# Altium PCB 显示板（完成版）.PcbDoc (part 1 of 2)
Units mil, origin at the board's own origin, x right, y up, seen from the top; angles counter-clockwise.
Board outline 5885.4 x 1803.57 mil, 2 copper layers (TOP, BOOTOM); 110 components, 88 nets, 770 pads, 302 vias.
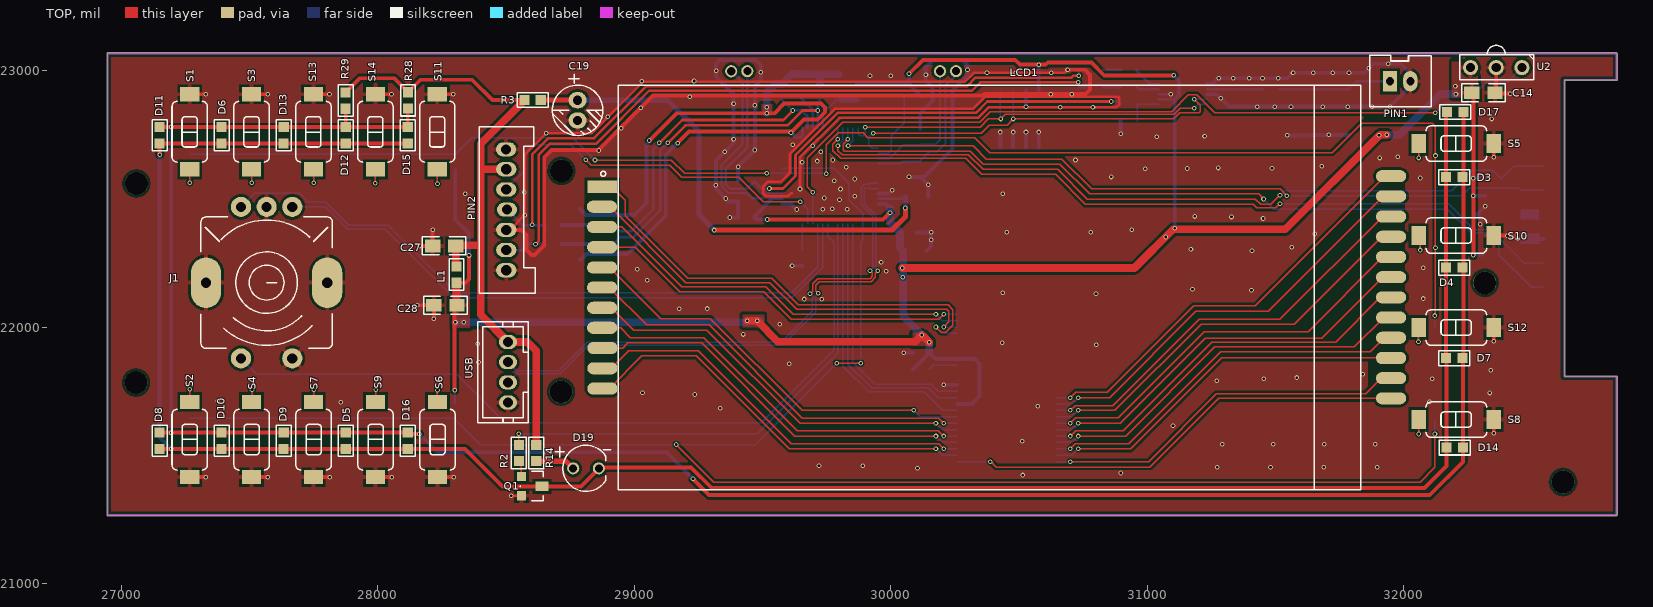
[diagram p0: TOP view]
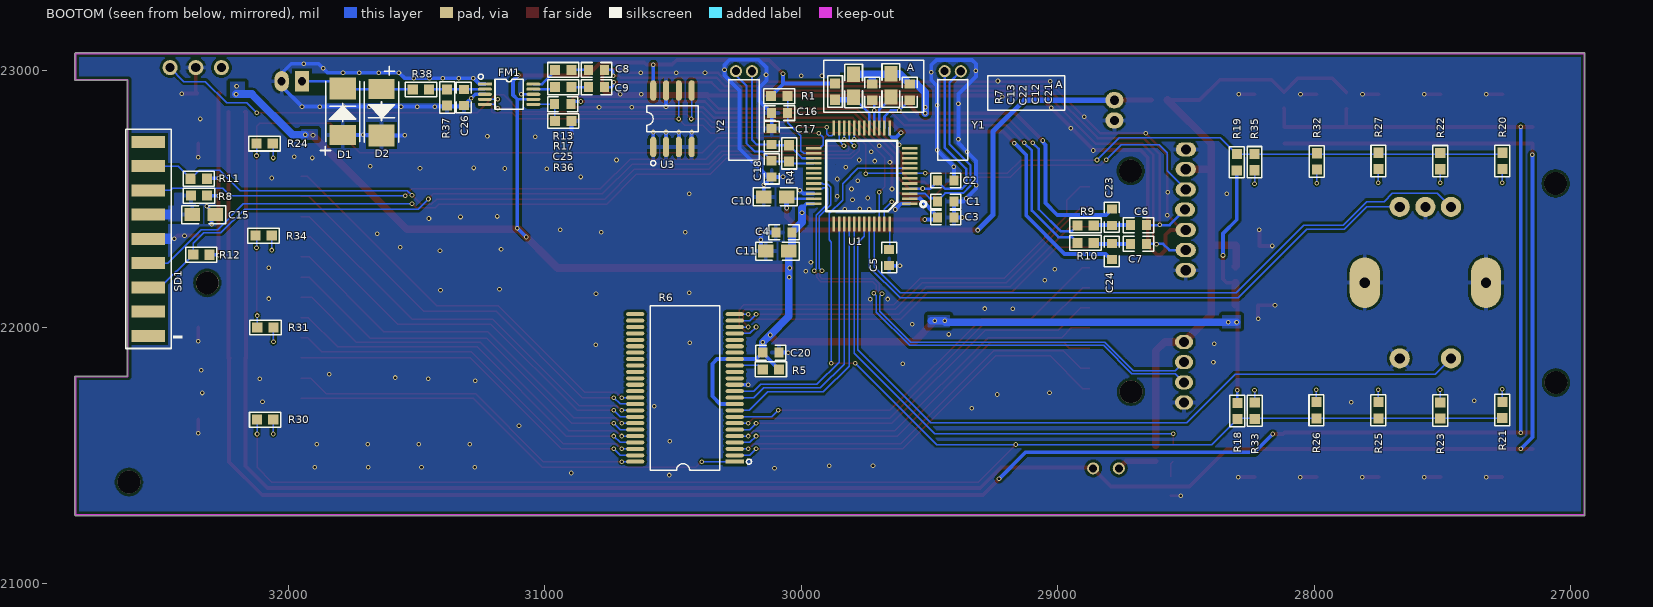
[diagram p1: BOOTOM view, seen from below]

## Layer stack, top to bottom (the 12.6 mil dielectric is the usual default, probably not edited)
TOP: signal copper 1.4
Dielectric: core 12.6, FR-4, Dk 4.8
BOOTOM: signal copper 1.4

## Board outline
26948.18,21265.88 28917.3,21265.88 ccw(c28917.3,21268.39) 28917.34,21265.88 32828.55,21265.88 ccw(c32828.55,21268.39) 32831.07,21268.39 32831.07,21807.05 ccw(c32828.55,21807.05) 32828.55,21809.56 32626.93,21809.56 32626.93,22962.36 32828.55,22962.36 ccw(c32828.55,22964.87) 32831.07,22964.87 32831.07,23066.93 ccw(c32828.55,23066.93) 32828.55,23069.45 26948.18,23069.45 ccw(c26948.18,23066.93) 26945.67,23066.93 26945.67,21295.39 ccw(c26948.18,21295.39) 26945.67,21295.36 26945.67,21268.39 ccw(c26948.18,21268.39)

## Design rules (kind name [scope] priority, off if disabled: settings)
Clearance VIA-POLY [(IsVia) vs INPOLY] p1: gap=5
Clearance POLY [(INPolygon)] p2: gap=10
Clearance ALL [All] p3: gap=5
DiffPairsRouting [(InDifferentialPairClass('90OM'))] p1: maxlimit=7 minlimit=7 mostfreqgap=7 maxuncoupledlength=500
HoleToHoleClearance [All] p1: gap=2 allowstackedmicrovias=TRUE
MatchedLengths DiffPair_90MatchedLengths [InDifferentialPair ('D_D')] p1: tolerance=1000 checknetsindiffpair=TRUE checkdiffpairvsdiffpair=TRUE checkothers=TRUE
NetAntennae [All] p1: netantennaetolerance=2
PlaneClearance [All] p1: clearance=8
PlaneConnect [All] p1: planeconnectstyle=Direct reliefexpansion=20 reliefentries=4 reliefconductorwidth=10 reliefairgap=10
PolygonConnect VIA-POLY0 [ISVIA] p1: connectstyle=Direct reliefconductorwidth=10 reliefentries=4 polygonreliefangle="90 Angle"
PolygonConnect [All] p2: connectstyle=Relief reliefconductorwidth=15 reliefentries=4 polygonreliefangle="90 Angle"
RoutingVias [All] p1: holewidth=10 width=18 viastyle="Through Hole" minholewidth=10 minwidth=18 maxholewidth=10 maxwidth=18
SilkToSilkClearance [All] p1: silktosilkclearance=2
SilkscreenOverComponentPads [All] p1: minsilkscreentomaskgap=2
SolderMaskExpansion [All] p1: expansion=2.5
Width Width90 [(InDifferentialPairClass('90OM'))] p1: maxlimit=5 minlimit=5 preferedwidth=5
Width PWR [InNetClass('PWR')] p2: maxlimit=60 minlimit=15 preferedwidth=15
Width ALLWidth [All] p3: maxlimit=5 minlimit=5 preferedwidth=5
21 further rules are at their usual default settings.

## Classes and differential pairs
differential pair class 90OM: D_D
net class SEG: COM0 COM1 COM2 COM3 SEG0 SEG1 SEG2 SEG3 SEG4 SEG5 SEG6 SEG7 SEG8 SEG9 SEG10 SEG11 SEG12 SEG13 SEG14 SEG15 SEG16 SEG17 SEG18
net class PWR: +5_0V AGND GND KEY_GND NetC10_1 SDVDD VDD33
differential pair D_D: +D+ -D-

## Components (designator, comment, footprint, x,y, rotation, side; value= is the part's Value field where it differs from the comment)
C1 "20P" C0603 29436.5,22490 r0 bottom locked
C2 "20P" C0603 29436.5,22572 r0 bottom locked
C3 "104" C0603 29436.5,22428 r180 bottom locked
C4 "104" C0603 30067.5,22370 r180 bottom locked
C5 "105" C0603 29657,22271.5 r90 bottom locked
C6 "105" C0603 28685.5,22398 r0 bottom locked
C7 "105" C0603 28685.5,22325 r0 bottom locked
C8 "105" C0603 30797.5,23003.05 r0 bottom locked
C9 "105" C0603 30797.5,22936.05 r0 bottom locked
C10 "106" C0805 30101,22508 r0 bottom locked
C11 "106" C0805 30093,22297 r180 bottom locked
C12 "106" C0805 29650,22942.5 r270 bottom locked
C13 "106" C0805 29796,22941 r90 bottom locked
C14 "106" C0805 32310,22914 r0 top locked
C15 "106" C0805 32329,22439 r0 bottom locked
C16 "NC" C0603 30084.5,22835 r180 bottom locked
C17 "10P" C0603 30115,22743.5 r270 bottom locked
C18 "10P" C0603 30115,22617.5 r90 bottom locked
C19 "220uF" EC_5 28779,22885 r270 top locked
C20 "0.1uF" C0603 30118.5,21901 r180 bottom locked
C21 "30" C0603 29577,22916.5 r270 bottom locked
C22 "30" C0603 29723,22916.5 r270 bottom locked
C23 "102" C0603 28789,22429 r270 bottom locked
C24 "102" C0603 28789,22295.5 r270 bottom locked
C25 "100pF" C0603 30929.62,22870 r180 bottom locked
C26 "18pF" C0603 31315,22895.5 r90 bottom locked
C27 "106" C0805 28259,22317 r180 top locked
C28 "106" C0805 28264,22086 r180 top locked
D1 "IN4148" DIODE 31787,22840.45 r270 bottom locked
D2 "IN4148" DIODE 31636,22838.45 r90 bottom locked
D3 "LED" R0603 32196.38,22585.05 r90 top locked
D4 "LED" R0603 32196.38,22232.37 r90 top locked
D5 "LED" R0603 27875.24,21557.62 r180 top locked
D6 "LED" R0603 27391.71,22748.38 r180 top locked
D7 "LED" R0603 32196.38,21879.68 r90 top locked
D8 "LED" R0603 27149.95,21557.62 r180 top locked
D9 "LED" R0603 27633.47,21557.62 r180 top locked
D10 "LED" R0603 27391.71,21557.62 r180 top locked
D11 "LED" R0603 27149.95,22748.38 r180 top locked
D12 "LED" R0603 27875.24,22748.38 r180 top locked
D13 "LED" R0603 27633.47,22748.38 r180 top locked
D14 "LED" R0603 32198.38,21531.05 r90 top locked
D15 "LED" R0603 28117,22748.38 r180 top locked
D16 "LED" R0603 28117,21557.62 r180 top locked
D17 "LED" R0603 32200.38,22839.05 r90 top locked
D19 "LED" BTLED 28804.97,21427.79 r0 top locked
FM1 "RDA5807M" RDA5807M 31138.51,22908.32 r180 bottom locked
J1 "编码器" ENCODE1 27567,22174 r0 top locked
L1 "" R0603 28306.95,22205.38 r180 top locked
LCD1 "23PINLCD" LCD22PIN 29864,22592.3 r0 top locked
PIN1 "2PIN" P2.0*2 32025,22959 r180 top locked
PIN2 "7PIN" P2.0*7 28500.49,22605.48 r0 top locked
Q1 "S8050" SOT-23 28600,21380.5 r270 top locked
R1 "10K" R0603 30085.62,22901.05 r270 bottom locked
R2 "10K" R0603 28550.05,21509.62 r180 top locked
R3 "2R2" R0603 28604,22886 r270 top locked
R4 "10M" R0603 30047,22678 r180 bottom locked
R5 "200R" R0603 30118.38,21835.95 r90 bottom locked
R6 "HT621B-A" YF1621 30471.69,21783.27 r0 bottom locked
R7 "4R7" R0603 29867.95,22918.62 r180 bottom locked
R8 "4R7" R0603 32347.38,22512.95 r90 bottom locked
R9 "5K1" R0603 28891.38,22396.95 r90 bottom locked
R10 "5K1" R0603 28891.38,22328.95 r90 bottom locked
R11 "4K7" R0603 32348.38,22578.95 r270 bottom locked
R12 "4K7" R0603 32338.38,22282.95 r90 bottom locked
R13 "1K" R0603 30927.62,23003.05 r90 bottom locked
R14 "1K" R0603 28618.05,21509.62 r180 top locked
R17 "1K" R0603 30927.62,22936.05 r90 bottom locked
R18 "30k" R0603 28299.95,21673.62 r180 bottom locked
R19 "30k" R0603 28302.05,22643.38 r0 bottom locked
R20 "3K3" r0603 27266.95,22648.62 r0 bottom locked
R21 "3K3" r0603 27267.05,21677.38 r180 bottom locked
R22 "68K" r0603 27508.95,22647.62 r0 bottom locked
R23 "7.5K" r0603 27509.05,21675.38 r180 bottom locked
R24 "120K" r0603 32091.62,22716.05 r270 bottom locked
R25 "12K" r0603 27750.05,21676.38 r180 bottom locked
R26 "47k" r0603 27991.55,21676.52 r180 bottom locked
R27 "120K" r0603 27749.95,22648.62 r0 bottom locked
R28 "330R" R0603 28118.05,22884.62 r0 top locked
R29 "330R" R0603 27875.05,22883.62 r180 top locked
R30 "20K 1%" R0603 32089.48,21640.05 r90 bottom locked
R31 "20K 1%" R0603 32088.62,21999.05 r90 bottom locked
R32 "20K 1%" R0603 27989.95,22646.62 r180 bottom locked
R33 "30K 1%" R0603 28232.05,21674.38 r0 bottom locked
R34 "30K 1%" R0603 32095.62,22357.05 r90 bottom locked
R35 "30K 1%" R0603 28232.95,22643.62 r180 bottom locked
R36 "2M" R0603 30927.62,22803.95 r90 bottom locked
R37 "100nH" R0603 31380.05,22895.38 r0 bottom locked
R38 "300nH" R0603 31482.38,22926.95 r270 bottom locked
S1 "P/P" K-BT 27267,22762 r90 top locked
S2 "P/P" K-BT 27267,21562 r270 top locked
S3 "PREV" K-BT 27508.25,22762 r90 top locked
S4 "MODE" K-BT 27508.5,21562 r270 top locked
S5 "" K-BT 32204,22716 r0 top locked
S6 "" K-BT 28233,21562 r270 top locked
S7 "" K-BT 27750,21562 r270 top locked
S8 "" K-BT 32204,21640 r0 top locked
S9 "" K-BT 27991.5,21562 r270 top locked
S10 "" K-BT 32204,22357.33 r0 top locked
S11 "" K-BT 28232,22762 r90 top locked
S12 "" K-BT 32204,21998.67 r0 top locked
S13 "" K-BT 27749.5,22762 r90 top locked
S14 "" K-BT 27990.75,22762 r90 top locked
SD1 "9PIN" SD24 32545,22344.49 r0 bottom locked
U1 "AX20" AX2005 29764,22590 r0 bottom locked
U2 "IR" IRDO 32359.77,23012.77 r0 top locked
U3 "24C02" SO-8 30502,22813 r90 bottom locked
USB "4PIN" P2.0*4 28506.76,21705.28 r90 top locked
Y1 "24M" 7.6M 29440.13,22998.43 r90 bottom locked
Y2 "32.768" 7.6M 30254,22998.43 r90 bottom locked

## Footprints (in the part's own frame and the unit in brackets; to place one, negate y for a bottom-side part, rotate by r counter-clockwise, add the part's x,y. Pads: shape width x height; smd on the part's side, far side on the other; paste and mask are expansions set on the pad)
7.6M [mm]
  round 1.2 hole 0.8: 1(-0.001,0.012) 2(-0.011,-1.578)
  silkscreen extent -8.81,-2.29 -0.81,0.71
AX2005 [mm]
  rect 1.5x0.25 smd: 1(-4.75,2.75) 2(-4.75,2.25) 3(-4.75,1.75) 4(-4.75,1.25) 5(-4.75,0.75) 6(-4.75,0.25) 7(-4.75,-0.25) 8(-4.75,-0.75) 9(-4.75,-1.25) 10(-4.75,-1.75) 11(-4.75,-2.25) 12(-4.75,-2.75) 25(4.75,-2.75) 26(4.75,-2.25) 27(4.75,-1.75) 28(4.75,-1.25) 29(4.75,-0.75) 30(4.75,-0.25) 31(4.75,0.25) 32(4.75,0.75) 33(4.75,1.25) 34(4.75,1.75) 35(4.75,2.25) 36(4.75,2.75)
  rect 0.25x1.5 smd: 13(-2.75,-4.75) 14(-2.25,-4.75) 15(-1.75,-4.75) 16(-1.25,-4.75) 17(-0.75,-4.75) 18(-0.25,-4.75) 19(0.25,-4.75) 20(0.75,-4.75) 21(1.25,-4.75) 22(1.75,-4.75) 23(2.25,-4.75) 24(2.75,-4.75) 37(2.75,4.75) 38(2.25,4.75) 39(1.75,4.75) 40(1.25,4.75) 41(0.75,4.75) 42(0.25,4.75) 43(-0.25,4.75) 44(-0.75,4.75) 45(-1.25,4.75) 46(-1.75,4.75) 47(-2.25,4.75) 48(-2.75,4.75)
  silkscreen extent -6.38,-3.5 3.5,3.5
BTLED [mm]
  round 1.2 hole 0.8: 1(-1.091,0.564) 2(1.449,0.564)
  silkscreen extent -2.84,-1.72 2.62,2.85
C0603 [mm]
  rect 0.9x1 smd: 1(-0.8,0) 2(0.8,0)
  silkscreen extent -1.5,-0.74 1.5,0.74
C0805 [mil]
  rect 60x50 smd: 1(-45,0) 2(45,0)
  silkscreen extent -85,-35 85,35
DIODE [mm]
  rect 2x2.6 smd: 1(2.3,0)
  rect 2.2x2.6 smd: 2(-2.3,0)
  silkscreen extent -3,-2.24 4.33,1.7
EC_5 [mm]
  oval 1.6x1.8 hole 0.9: 1(-0.001,0.006) 2(1.999,0.006)
  silkscreen extent -2.57,-2.49 3.5,2.51
ENCODE1 [mm]
  round 2 hole 1: 1(-2.54,7.5) 2(0,7.5) 3(2.54,7.5) 4(2.54,-7.5) 5(-2.54,-7.5)
  oval 2.997x5.004 hole 1.016: 6(6,0) 7(-6,0)
  silkscreen extent -6.5,-6.5 6.5,6.5
IRDO [mm]
  round 1.5 hole 0.9: 1(2.546,-0.02) 2(0.006,-0.02) 3(-2.534,-0.02)
  silkscreen extent -3.59,-1.22 3.71,2.18
K-BT [mm]
  rect 1.4x1.9 smd: 1(-3.712,0) 2(3.712,0)
  silkscreen extent -2.99,-1.75 3.01,1.75
LCD22PIN [mm]
  rect 3x1.2 smd: 1(-25.095,-1.127)
  oval 3x1.2 smd: 2(-25.146,-3.108) 3(-25.121,-5.115) 4(-25.121,-7.121) 5(-25.121,-9.128) 6(-25.121,-11.109) 7(-25.121,-13.116) 8(-25.121,-15.097) 9(-25.095,-17.104) 10(-25.095,-19.11) 11(-25.095,-21.117) 12(52.984,-22.084) 13(52.984,-20.084) 14(52.984,-18.084) 15(52.984,-16.084) 16(52.984,-14.084) 17(52.984,-12.084) 18(52.984,-10.084) 19(52.984,-8.084) 20(52.984,-6.084) 21(52.984,-4.084) 22(52.984,-2.084) 23(52.984,-0.084)
  silkscreen extent -25.27,-31.12 49.99,8.93
P2.0*2 [mm]
  oval 1.4x2 hole 0.8: 1(0,0)
  rect 1.4x2 hole 0.8: 2(2,0)
  silkscreen extent -2.08,-2.57 4.01,2.51
P2.0*4 [mm]
  oval 1.4x1.8 hole 1: 1(0.031,-0.032) 2(2.031,-0.032) 3(4.031,-0.032) 4(6.031,-0.032)
  silkscreen extent -1.97,-2.03 8.03,2.97
P2.0*7 [mm]
  oval 2x1.4 hole 1: 1(0,2.235) 2(0.013,0.266) 3(0.013,-1.734) 4(0.087,-3.734) 5(0.013,-5.734) 6(0.013,-7.734) 7(0.013,-9.734)
  silkscreen extent -2.67,-11.99 2.88,4.47
R0603 [mm]
  rect 1x1 smd: 1(-0.001,-0.803) 2(0.001,0.803)
  silkscreen extent -0.74,-1.55 0.74,1.55
r0603 [mm]
  rect 1x1 smd: 1(-0.001,-0.803) 2(0.001,0.803)
  silkscreen extent -0.74,-1.55 0.74,1.55
RDA5807M [mm]
  rect 1.4x0.3 smd: 1(-2.4,1)
  oval 1.4x0.3 smd: 2(-2.4,0.5) 3(-2.4,0) 4(-2.4,-0.5) 5(-2.4,-1) 6(2.4,-1) 7(2.4,-0.5) 8(2.4,0) 9(2.4,0.5) 10(2.4,1)
  silkscreen extent -3.06,-1.5 1.4,2
SD24 [mm]
  rect 3.3x1.2 smd: 1(0,9.6) 2(0,7.2) 3(0,4.8) 4(0,2.4) 5(0,0) 6(0,-2.4) 7(0,-4.8) 8(0,-7.2) 9(0,-9.6)
  silkscreen extent -3.39,-10.85 2.25,10.85
SO-8 [mil]
  oval 80x24 smd: 1(-110,75) 2(-110,25) 3(-110,-25) 4(-110,-75) 5(110,-75) 6(110,-25) 7(110,25) 8(110,75)
  silkscreen extent -183,-100 50,100
SOT-23 [mil]
  rect 36x36 smd: 1(-37.5,-40) 2(37.5,-40)
  rect 36x50 smd: 3(0.5,40)
  silkscreen extent -58,-45 58,45
YF1621 [mm]
  rect 1.8x0.4 smd: 1(-5.402,7.805)
  oval 1.8x0.4 smd: 2(-5.402,7.17) 3(-5.402,6.535) 4(-5.402,5.9) 5(-5.402,5.265) 6(-5.402,4.63) 7(-5.402,3.995) 8(-5.402,3.36) 9(-5.402,2.725) 10(-5.402,2.09) 11(-5.402,1.455) 12(-5.402,0.82) 13(-5.402,0.185) 14(-5.402,-0.45) 15(-5.402,-1.085) 16(-5.402,-1.72) 17(-5.402,-2.355) 18(-5.402,-2.99) 19(-5.402,-3.625) 20(-5.402,-4.26) 21(-5.402,-4.895) 22(-5.402,-5.53) 23(-5.402,-6.165) 24(-5.402,-6.8) 25(4.453,-6.8) 26(4.453,-6.165) 27(4.453,-5.53) 28(4.453,-4.895) 29(4.453,-4.26) 30(4.453,-3.625) 31(4.453,-2.99) 32(4.453,-2.355) 33(4.453,-1.72) 34(4.453,-1.085) 35(4.453,-0.45) 36(4.453,0.185) 37(4.453,0.82) 38(4.453,1.455) 39(4.453,2.09) 40(4.453,2.725) 41(4.453,3.36) 42(4.453,3.995) 43(4.453,4.63) 44(4.453,5.265) 45(4.453,5.9) 46(4.453,6.535) 47(4.453,7.17) 48(4.453,7.805)
  silkscreen extent -7.06,-7.65 2.98,8.65

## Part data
C1 C2 C3 C4 C5 C6 C7 C8 C9 C10 C11 C12 C13 C14 C15 C16 C17 C18 C20 C21 C22 C23 C24 C25 C26 C27 C28: library part CAP, "Capacitor"
C19: library part ELECTRO1, "Electrolytic Capacitor"
D1 D2: library part DIODE, "Diode"
J1: library part ENCODE
L1 R1 R2 R3 R4 R5 R7 R8 R9 R10 R11 R12 R13 R14 R17 R18 R19 R20 R21 R22 R23 R24 R25 R26 R27 R28 R29 R30 R31 R32 R33 R34 R35 R36 R37 R38: library part RES2
Q1: library part NPN, "NPN Transistor"
S1 S2 S3 S4 S5 S6 S7 S8 S9 S10 S11 S12 S13 S14: library part SW-PB
U3: library part EEPROM-8
Y1 Y2: library part CRYSTAL

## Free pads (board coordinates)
  round 88.98 hole 88.98 unplated: 0(27058.25,21784.48) 0(27059.33,22560.3) 0(28714.55,21748.54) 0(28715.92,22609.5) 0(32315.31,22172.96) 0(32620.46,21396.66)
  round 10 on Mech2: 1(26822.18,21328.39) 1(26822.18,23006.93) 1(26832.18,21268.39) 1(26832.18,23066.93) 1(26842.18,21268.39) 1(26842.18,21268.39) 1(26842.18,21268.39) 1(26842.18,21940.72) 1(26842.18,22362.6) 1(26842.18,23066.93) 1(26842.18,23066.93) 1(26842.18,23066.93) 1(26862.18,21328.39) 1(26862.18,23006.93) 1(26935.68,21268.39) 1(26948.18,21123.39) 1(26948.18,21133.39) 1(26948.18,21133.39) 1(26948.18,21133.39) 1(26948.18,21282.89) 1(26948.71,23066.93) 1(27008.18,21113.39) 1(27008.18,21153.39) 1(29636.44,21133.39) 1(30108.3,21133.39) 1(32768.55,21113.39) 1(32768.55,21153.39) 1(32828.55,21123.39) 1(32828.55,21133.39) 1(32828.55,21133.39) 1(32828.55,21133.39) 1(32828.55,21255.89)
  round 5 on Mech2: 1(26948.18,21268.39) 1(26948.18,21268.39) 1(26948.18,21268.39) 1(26948.18,21268.39) 1(26948.18,21268.39) 1(26948.18,21268.39) 1(26948.18,21268.39) 1(26948.18,21268.39) 1(26948.18,21279.39) 1(26948.18,21279.39) 1(26948.18,21279.39) 1(26948.18,21279.39) 1(26948.18,21295.39) 1(26948.18,21295.39) 1(26948.18,21295.39) 1(26948.18,21295.39) 1(26948.18,21295.39) 1(26948.18,21295.39) 1(26948.18,21295.39) 1(26948.18,21295.39) 1(26948.18,23066.93) 1(26948.18,23066.93) 1(26948.18,23066.93) 1(26948.18,23066.93) 1(26948.18,23066.93) 1(26948.18,23066.93) 1(26948.18,23066.93) 1(26948.18,23066.93) 1(26948.18,21268.39) 1(26948.18,21268.39) 1(26948.18,21268.39) 1(26948.18,21268.39) 1(26961.21,23066.93) 1(26961.21,23066.93) 1(26961.21,23066.93) 1(26961.21,23066.93) 1(27311.18,23066.93) 1(27311.18,23066.93) 1(27311.18,23066.93) 1(27311.18,23066.93) 1(28785.69,23066.93) 1(28785.69,23066.93) 1(28785.69,23066.93) 1(28785.69,23066.93) 1(28912.19,21268.39) 1(28912.19,21268.39) 1(28912.19,21268.39) 1(28912.19,21268.39) 1(28915.33,23066.93) 1(28915.33,23066.93) 1(28915.33,23066.93) 1(28915.33,23066.93) 1(28917.3,21268.39) 1(28917.3,21268.39) 1(28917.3,21268.39) 1(28917.3,21268.39) 1(29149.59,21268.39) 1(29149.59,21268.39) 1(29149.59,21268.39) 1(29149.59,21268.39) 1(29162.09,23066.93) 1(29162.09,23066.93) 1(29162.09,23066.93) 1(29162.09,23066.93) 1(29263.89,23066.93) 1(29263.89,23066.93) 1(29263.89,23066.93) 1(29263.89,23066.93) 1(30066.59,21268.39) 1(30066.59,21268.39) 1(30066.59,21268.39) 1(30066.59,21268.39) 1(31765.19,21268.39) 1(31765.19,21268.39) 1(31765.19,21268.39) 1(31765.19,21268.39) 1(31777.54,21268.39) 1(31777.54,21268.39) 1(31777.54,21268.39) 1(31777.54,21268.39) 1(32010.34,21268.39) 1(32010.34,21268.39) 1(32010.34,21268.39) 1(32010.34,21268.39) 1(32112.79,21268.39) 1(32112.79,21268.39) 1(32112.79,21268.39) 1(32112.79,21268.39) 1(32624.41,21807.05) 1(32624.41,21807.05) 1(32624.41,21807.05) 1(32624.41,21807.05) 1(32624.41,21807.05) 1(32624.41,21807.05) 1(32624.41,21807.05) 1(32624.41,21807.05) 1(32624.41,22964.67) 1(32624.41,22964.67) 1(32624.41,22964.67) 1(32624.41,22964.67) 1(32624.41,22964.87) 1(32686.82,22964.87) 1(32686.82,22964.87) 1(32686.82,22964.87) 1(32686.82,22964.87) 1(32686.82,22964.87) 1(32687.41,21807.05) 1(32687.41,21807.05) 1(32687.41,21807.05) 1(32687.41,21807.05) 1(32687.41,21807.05) 1(32687.41,21807.05) 1(32687.41,21807.05) 1(32687.41,21807.05) 1(32828.27,22964.87) 1(32828.27,22964.87) 1(32828.27,22964.87) 1(32828.27,22964.87) 1(32828.55,21268.39) 1(32828.55,21268.39) 1(32828.55,21268.39) 1(32828.55,21268.39) 1(32828.55,21268.39) 1(32828.55,21268.39) 1(32828.55,21268.39) 1(32828.55,21268.39) 1(32828.55,21268.39) 1(32828.55,21268.39) 1(32828.55,21295.59) 1(32828.55,21295.59) 1(32828.55,21295.59) 1(32828.55,21295.59) 1(32828.55,21344.39) 1(32828.55,21344.39) 1(32828.55,21344.39) 1(32828.55,21344.39) 1(32828.55,21528.39) 1(32828.55,21528.39) 1(32828.55,21807.24) 1(32828.55,21807.24) 1(32828.55,21807.24) 1(32828.55,21807.24) 1(32828.55,22964.87) 1(32828.55,22964.87) 1(32828.55,22964.87) 1(32828.55,22964.87) 1(32828.55,23066.93) 1(32828.55,23066.93) 1(32828.55,23066.93) 1(32828.55,23066.93) 1(32828.55,23067.25) 1(32828.55,23067.25) 1(32828.55,23067.25) 1(32828.55,23067.25) 1(32829.14,21807.05) 1(32829.14,21807.05) 1(32829.14,21807.05) 1(32829.14,21807.05)
  round 6 on Mech2: 1(27009.55,21784.48) 1(27009.55,21784.48) 1(27010.63,22560.3) 1(27010.63,22560.3) 1(27106.95,21784.48) 1(27106.95,21784.48) 1(27108.03,22560.3) 1(27108.03,22560.3) 1(28665.85,21748.54) 1(28665.85,21748.54) 1(28667.22,22609.5) 1(28667.22,22609.5) 1(28763.25,21748.54) 1(28763.25,21748.54) 1(28764.62,22609.5) 1(28764.62,22609.5) 1(32266.61,22172.96) 1(32266.61,22172.96) 1(32364.01,22172.96) 1(32364.01,22172.96) 1(32571.76,21396.66) 1(32571.76,21396.66) 1(32669.16,21396.66) 1(32669.16,21396.66)
  round 2 on Mech2: 1(27237.06,22702.72) 1(27237.06,22702.72) 1(27237.06,22714.53) 1(27237.06,22714.53) 1(27237.06,22820.83) 1(27237.06,22820.83) 1(27237.8,21500.76) 1(27237.8,21500.76) 1(27237.8,21618.87) 1(27237.8,21618.87) 1(27296.12,22702.72) 1(27296.12,22702.72) 1(27296.12,22820.83) 1(27296.12,22820.83) 1(27296.85,21500.76) 1(27296.85,21500.76) 1(27296.85,21607.06) 1(27296.85,21607.06) 1(27296.85,21618.87) 1(27296.85,21618.87) 1(27312.81,21920.89) 1(27312.81,21920.89) 1(27312.81,22115.26) 1(27312.81,22115.26) 1(27312.81,22235.85) 1(27312.81,22237.26) 1(27312.81,22432.7) 1(27312.81,22432.7) 1(27336.98,22432.7) 1(27336.98,22432.7) 1(27362.02,22115.26) 1(27362.02,22115.26) 1(27362.02,22235.85) 1(27362.02,22235.85) 1(27478.37,22702.72) 1(27478.37,22702.72) 1(27478.37,22714.53) 1(27478.37,22714.53) 1(27478.37,22820.83) 1(27478.37,22820.83) 1(27478.69,21500.76) 1(27478.69,21500.76) 1(27478.69,21618.87) 1(27478.69,21618.87) 1(27537.42,22702.72) 1(27537.42,22702.72) 1(27537.42,22820.83) 1(27537.42,22820.83) 1(27537.74,21500.76) 1(27537.74,21500.76) 1(27537.74,21607.06) 1(27537.74,21607.06) 1(27537.74,21618.87) 1(27537.74,21618.87) 1(27719.68,22702.72) 1(27719.68,22702.72) 1(27719.68,22714.53) 1(27719.68,22714.53) 1(27719.68,22820.83) 1(27719.68,22820.83) 1(27720.05,21500.76) 1(27720.05,21500.76) 1(27720.05,21618.87) 1(27720.05,21618.87) 1(27775.41,22117.74) 1(27775.41,22117.74) 1(27775.41,22235.85) 1(27775.41,22235.85) 1(27778.73,22702.72) 1(27778.73,22702.72) 1(27778.73,22820.83) 1(27778.73,22820.83) 1(27779.11,21500.76) 1(27779.11,21500.76) 1(27779.11,21607.06) 1(27779.11,21607.06) 1(27779.11,21618.87) 1(27779.11,21618.87) 1(27824.62,21920.89) 1(27824.62,21920.89) 1(27824.62,22117.74) 1(27824.62,22117.74) 1(27824.62,22235.85) 1(27824.62,22235.85) 1(27824.62,22432.7) 1(27824.62,22432.7) 1(27960.47,21500.76) 1(27960.47,21500.76) 1(27960.47,21618.87) 1(27960.47,21618.87) 1(27960.84,22702.71) 1(27960.84,22702.71) 1(27960.84,22714.53) 1(27960.84,22714.53) 1(27960.84,22820.82) 1(27960.84,22820.82) 1(28019.53,21500.76) 1(28019.53,21500.76) 1(28019.53,21607.06) 1(28019.53,21607.06) 1(28019.53,21618.87) 1(28019.53,21618.87) 1(28019.9,22702.71) 1(28019.9,22702.71) 1(28019.9,22820.82) 1(28019.9,22820.82) 1(28202.29,22702.72) 1(28202.29,22702.72) 1(28202.29,22714.53) 1(28202.29,22714.53) 1(28202.29,22820.83) 1(28202.29,22820.83) 1(28203.42,21500.77) 1(28203.42,21500.77) 1(28203.42,21618.88) 1(28203.42,21618.88) 1(28261.34,22702.72) 1(28261.34,22702.72) 1(28261.34,22820.83) 1(28261.34,22820.83) 1(28262.47,21500.77) 1(28262.47,21500.77) 1(28262.47,21607.07) 1(28262.47,21607.07) 1(28262.47,21618.88) 1(28262.47,21618.88) 1(28937.99,21369.26) 1(28937.99,21369.26) 1(28937.99,22946.26) 1(28937.99,22946.26) 1(31831.99,21369.26) 1(31831.99,21369.26) 1(31831.99,22946.26) 1(31831.99,22946.26) 1(32146.13,21610.23) 1(32146.13,21610.23) 1(32146.13,21669.29) 1(32146.13,21669.29) 1(32146.13,21969.23) 1(32146.13,21969.23) 1(32146.13,22028.29) 1(32146.13,22028.29) 1(32146.13,22328.23) 1(32146.13,22328.23) 1(32146.13,22387.29) 1(32146.13,22387.29) 1(32146.13,22687.23) 1(32146.13,22687.23) 1(32146.13,22746.29) 1(32146.13,22746.29) 1(32157.94,21669.29) 1(32157.94,21669.29) 1(32157.94,22028.29) 1(32157.94,22028.29) 1(32157.94,22387.29) 1(32157.94,22387.29) 1(32157.94,22746.29) 1(32157.94,22746.29) 1(32264.24,21610.23) 1(32264.24,21610.23) 1(32264.24,21669.29) 1(32264.24,21669.29) 1(32264.24,21969.23) 1(32264.24,21969.23) 1(32264.24,22028.29) 1(32264.24,22028.29) 1(32264.24,22328.23) 1(32264.24,22328.23) 1(32264.24,22387.29) 1(32264.24,22387.29) 1(32264.24,22687.23) 1(32264.24,22687.23) 1(32264.24,22746.29) 1(32264.24,22746.29) 1(32458.1,21919.79) 1(32458.1,21919.79) 1(32458.1,22774.12) 1(32458.1,22774.12) 1(32635.27,21919.79) 1(32635.27,21919.79) 1(32635.27,22774.12) 1(32635.27,22774.12)

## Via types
v1: diameter 18, hole 10, TOP to BOOTOM, tented both sides, 302 vias

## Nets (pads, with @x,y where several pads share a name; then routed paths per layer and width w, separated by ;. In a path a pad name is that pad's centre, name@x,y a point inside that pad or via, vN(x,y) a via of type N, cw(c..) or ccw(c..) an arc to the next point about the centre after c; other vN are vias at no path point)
+5_0V: C27.1 L1.1 PIN2.2 R3.1 R14.1 R28.2 R29.1 USB.4 | length 2624.4
  TOP w15: R29.1@27875.1,22915.25 27930.86,22971 28063.35,22971 R28.2@28118.1,22916.25 28166.86,22965 28368,22965 28446.95,22886.05 R3.1@28572.38,22886.05
  TOP w30: L1.1@28307,22237 28304,22240 C27.1@28304,22317 28307,22320 28402,22320 ; PIN2.2@28501,22615.96 28402,22615.96 ; R3.1@28572.38,22886.05 28402,22715.68 28402,22615.96 ; R14.1@28618.1,21541.25 28618.1,21907.9 28583.26,21942.74 USB.4@28508,21942.74 28402,22048.74 28402,22320 ; 28402,22320 28402,22615.96
ADKEY1: R19.1 R20.1 R22.1 R24.1 R27.1 R31.2 R32.2 R34.2 R35.2 U1.7 | length 6047.4
  TOP w5: v1(28847,22652) 29144,22652 29196.16,22599.84 v1(29515.84,22599.84) ; v1(29749,22599) 29749,22712 29795.12,22758.12 29891.88,22758.12 29911,22739 30327,22739 30385,22681 31721,22681 31836,22796 32110,22796 32123.25,22782.75 v1(32123.25,22669.46) v1(32123.25,22310.46) 32123.25,22048.75 v1(32120.25,22045.75)
  BOOTOM w5: R20.1@27266.9,22680.25 27271.9,22675.25 R35.2@28232.9,22675.25 28233.14,22675 R19.1@28302,22675 28366,22739 28760,22739 v1(28847,22652) ; v1(29515.84,22599.84) U1.7@29576.99,22599.84 29748.16,22599.84 v1(29749,22599) ; v1(32120.25,22045.75) R31.2@32120.25,21999.1 R31.2@32123.25,21999.1 ; R34.2@32120.25,22357.1 32123.25,22357.1 v1(32123.25,22310.46) ; R24.1@32120.25,22716.1 R24.1@32123.25,22716.1 v1(32123.25,22669.46)
ADKEY2: R18.1 R21.1 R23.1 R25.1 R26.1 R30.2 R33.2 U1.8 | length 7037.9
  TOP w5: v1(29163,21543) 29310,21396 32063,21396 32121.11,21454.11 v1(32121.11,21584) ; v1(29789,21860) v1(29883,21860)
  BOOTOM w5: R21.1@27267.1,21645.75 28296.25,21645.75 R18.1@28300,21642 ; R33.2@28232.1,21642.75 R33.2@28232.86,21642 ; R18.1@28304,21646 R18.1@28300,21642 ; U1.8@29576.99,22619.53 29779.47,22619.53 29839,22560 29839,22496 29891,22444 29891,22341 29882,22332 29882,21861 v1(29883,21860) ; v1(29789,21860) 29472,21543 v1(29163,21543) 28399,21543 R18.1@28300,21642 ; v1(32121.11,21584) R30.2@32121.11,21640.1
AGND: C12.1 C13.2 C21.1 C22.1 C23.1 C24.2 U1.13 | length 3147.5
  TOP w15: v1(29059,22728) 29165,22834 v1(29516,22834) 29546,22834 29584,22872 29728,22872 29743,22857 29743,22838 29715,22810 29662,22810 v1(29611,22759) 29607,22763 29214,22763 v1(29169,22718)
  BOOTOM w10: 29647,22741 29655.73,22749.73 U1.13@29655.73,22777.01
  BOOTOM w15: C24.2@28789,22264 28792,22264 28814,22286 28974,22286 29123,22435 29123,22672 v1(29169,22718) ; C23.1@28789,22460.5 28811.5,22438 29002,22438 29048,22484 29048,22711 v1@29060,22723 ; v1(29611,22759) 29629,22741 29647,22741
  BOOTOM w30: v1(29516,22834) v1(29516,22858) 29516,22915 29548.99,22947.99 C21.1@29577,22947.99 29616.5,22987.5 C12.1@29650,22987.5 ; C12.1@29650,22986 29720,22986 ; C22.1@29723,22947.99 29723,22983 29720,22986 ; C13.2@29796,22986 29720,22986
CLK: C1.2 U1.3 Y1.2 | length 763
  BOOTOM w8: Y1.2@29378,22998 29422,22954 29422,22713 29340,22631 29340,22552 29369,22523 29439,22523 29459,22503 29499,22503 29517.1,22521.1 U1.3@29576.99,22521.1
COM0: LCD1.1 R6.21 | length 1838.3
  TOP w5: LCD1.1@28876,22547.93 28912.07,22547.93 28965,22495 28965,22434.44 29208.44,22191 29536,22191 29640,22087 30223,22087 30241,22069 30241,22007 30215,21981 30196,21981 v1(30176,22001)
  BOOTOM w5: v1(30176,22001) 30201,21976 R6.21@30259,21976
COM1: LCD1.2 R6.22 | length 1643.3
  TOP w5: LCD1.2@28874,22469.93 28905.47,22469.93 29201.4,22174 29528.96,22174 29632.96,22070 30218,22070 30226,22062 30226,22021 v1(30206,22001)
  BOOTOM w5: v1(30206,22001) R6.22@30259,22001
COM2: LCD1.3 R6.23 | length 1535.2
  TOP w5: LCD1.3@28875,22390.93 28951.94,22390.93 29184.87,22158 29512.43,22158 29619.43,22051 v1(30176,22051)
  BOOTOM w5: v1(30176,22051) 30201,22026 R6.23@30259,22026
COM3: LCD1.4 R6.24 | length 1507.8
  TOP w5: LCD1.4@28875,22311.93 29004.07,22311.93 29177,22139 29504.56,22139 29611.56,22032 30187,22032 v1(30206,22051)
  BOOTOM w5: v1(30206,22051) R6.24@30259,22051
D+: U1.33 USB.2 | length 2101.3
  TOP w5: v1(29717,22132) 29707,22142 29707,22164 29721,22178 29923.97,22178 29940,22194.03 29940,22211 v1(29949,22220)
  BOOTOM w5: USB.2@28508,21785.26 28541.37,21818.63 28710.6,21818.63 28820.97,21929 29576.97,21929 29707,22059.03 29707,22122 v1(29717,22132) ; v1(29949,22220) 29941,22228 29941,22436.97 29896,22481.97 29896,22540.03 29900.6,22544.63 29914.16,22544.63 29918,22540.79 U1.33@29951.01,22540.79
D-: U1.32 USB.3 | length 2101.2
  TOP w5: v1(29685,22130) 29695,22140 29695,22168.97 29716.03,22190 29919,22190 29928,22199 29928,22212 v1(29919,22221)
  BOOTOM w5: USB.3@28508,21864 28541.37,21830.63 28705.63,21830.63 28816,21941 29572,21941 29693.85,22062.85 29693.85,22121.15 v1(29685,22130) ; v1(29919,22221) 29929,22231 29929,22432 29884,22477 29884,22545 29895.63,22556.63 29914.16,22556.63 29918,22560.47 U1.32@29951.01,22560.47
DAC_L: C6.1 C8.1 PIN2.4 | length 2759.8
  TOP w10: v1(28602,22399) 28602,22673 28666,22737 28843,22737 29045,22939 30297,22939 30331,22973 30705,22973 30713,22981 v1(30732,22981)
  BOOTOM w10: PIN2.4@28503.91,22458.48 28564.39,22398 C6.1@28654.01,22398 ; v1(30732,22981) 30732,22998 30737.05,23003.05 C8.1@30766,23003.05
DAC_R: C7.1 C9.1 PIN2.6 | length 2788
  TOP w10: v1(28615,22323) 28627,22335 28627,22672 28670,22715 28851,22715 29058,22922 30316,22922 30349,22955 v1(30731,22955)
  BOOTOM w10: PIN2.6@28501,22301 28565,22301 28589,22325 C7.1@28654.01,22325 ; v1(30731,22955) 30731,22943 30737.95,22936.05 C9.1@30766,22936.05
DACL: C21.2 R9.2 U1.14 | length 1214.5
  TOP w10: v1(29098,22719) 29187,22808 29581,22808 v1(29618,22845)
  BOOTOM w10: R9.2@28923,22397 28946,22374 28988,22374 29074,22460 29074,22576 ; 29074,22584 29074,22576 ; v1(29098,22719) 29074,22695 29074,22576 ; C21.2@29577,22885 29616,22846 29651,22846 29675.42,22821.58 U1.14@29675.42,22777.01
DACR: C22.2 R10.2 U1.16 | length 1254.2
  TOP w10: v1(29131,22719) 29199,22787 29597,22787 29655,22845 v1(29715,22845)
  BOOTOM w10: R10.2@28923,22329 28945,22351 28997.04,22351 29101,22454.96 29101,22689 v1(29131,22719) ; U1.16@29714.79,22777.01 29714.79,22876.79 C22.2@29723,22885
